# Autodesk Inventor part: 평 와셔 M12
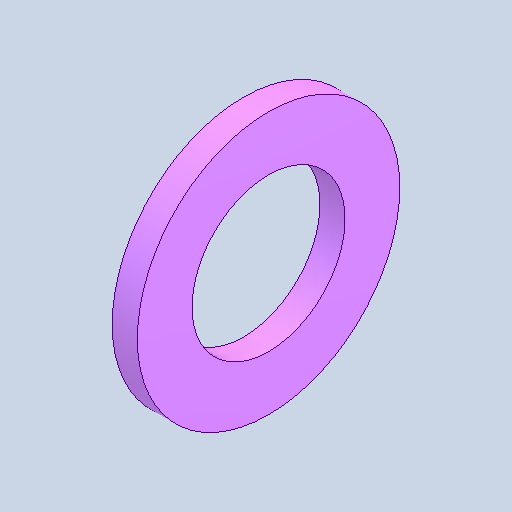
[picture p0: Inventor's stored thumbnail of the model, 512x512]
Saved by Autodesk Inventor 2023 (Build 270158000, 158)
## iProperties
Created: 2026-06
Part Number: 평 와셔 M12
Material: 강철, 연강
Description: 평면 와셔
Document SubType Name: Modeling
Designer: home
Density: 7.85 g/cm^3
Appearance: 기본값
Author: jhkim
Sending System: Autodesk Inventor 2027
Preprocessor: ST-DEVELOPER v20.1
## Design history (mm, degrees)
feature "Solid1"
node "솔리드1"
